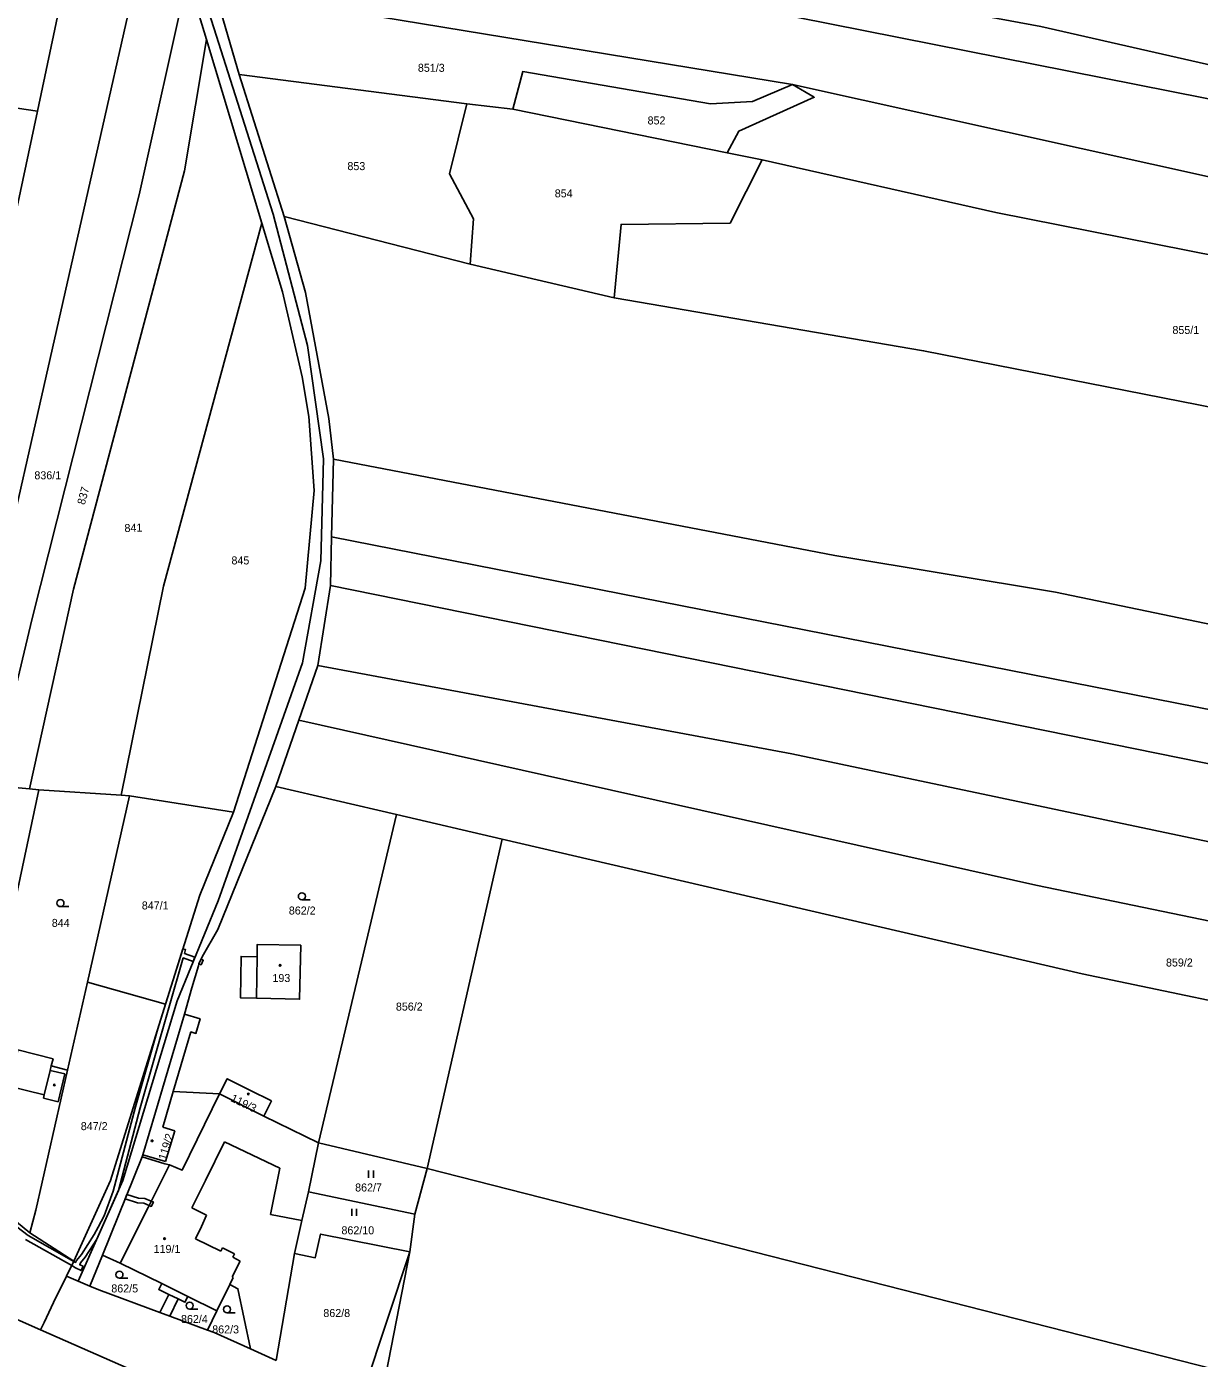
# Model space of a CAD drawing. Extents: x -776734 to -748832, y -1118122 to -976986.
# Drawn here: x -752662.5 to -752413.4, y -1114263.1 to -1113980.3 of the extents above; entities that cross this region are included whole.
import ezdxf

# ---------------------------------------------------------------- set-up
doc = ezdxf.new("R2010")
doc.units = 0
for name, color, linetype in [('KM_Hranice obce', 7, 'Continuous'), ('KM_Hranice parcel', 7, 'Continuous'), ('KM_Parcelní čísla', 7, 'Continuous'), ('KM_Vnitřní kresba', 7, 'Continuous'), ('KM_Věcná břemena k části', 7, 'Continuous'), ('KM_Značky budov', 7, 'Continuous'), ('KM_Značky kultur', 7, 'Continuous')]:
    doc.layers.add(name, color=color, linetype=linetype)

msp = doc.modelspace()

# ---------------------------------------------------------------- linework, layer by layer
at = {"layer": 'KM_Hranice obce'}
for p, q in [((-752624.32, -1113982.98), (-752628.32, -1113969.72)), ((-752624.32, -1113982.98), (-752628.32, -1113969.72)), ((-752612.54, -1114022), (-752624.32, -1113982.98)), ((-752612.54, -1114022), (-752624.32, -1113982.98)), ((-752618.58, -1114147.1), (-752603.37, -1114099.53)), ((-752618.58, -1114147.1), (-752603.37, -1114099.53)), ((-752618.58, -1114147.1), (-752625.74, -1114164.68)), ((-752618.58, -1114147.1), (-752625.74, -1114164.68)), ((-752625.74, -1114164.68), (-752632.98, -1114187.86)), ((-752625.74, -1114164.68), (-752632.98, -1114187.86)), ((-752632.98, -1114187.86), (-752644.66, -1114225.27)), ((-752632.98, -1114187.86), (-752644.66, -1114225.27)), ((-752644.66, -1114225.27), (-752652.49, -1114242.44)), ((-752644.66, -1114225.27), (-752652.49, -1114242.44)), ((-752654.02, -1114245.64), (-752652.49, -1114242.44)), ((-752654.02, -1114245.64), (-752652.49, -1114242.44)), ((-752637.21, -1114266.89), (-752659.53, -1114257.03)), ((-752637.21, -1114266.89), (-752659.53, -1114257.03))]:
    msp.add_line(p, q, dxfattribs=at)
for points in [[(-752603.37, -1114099.53), (-752601.44, -1114078.8), (-752602.54, -1114063.06), (-752603.98, -1114054.63), (-752608.14, -1114036.59), (-752612.54, -1114022)], [(-752603.37, -1114099.53), (-752601.44, -1114078.8), (-752602.54, -1114063.06), (-752603.98, -1114054.63), (-752608.14, -1114036.59), (-752612.54, -1114022)], [(-752654.02, -1114245.64), (-752656.77, -1114251.23), (-752658.78, -1114255.48), (-752659.53, -1114257.03)], [(-752654.02, -1114245.64), (-752656.77, -1114251.23), (-752658.78, -1114255.48), (-752659.53, -1114257.03)]]:
    msp.add_lwpolyline(points, dxfattribs=at)
at = {"layer": 'KM_Hranice parcel'}
for p, q in [((-752622.66, -1113972.37), (-752499.87, -1113992.53)), ((-752622.66, -1113972.37), (-752617.37, -1113990.44)), ((-752617.37, -1113990.44), (-752569.04, -1113996.68)), ((-752617.37, -1113990.44), (-752607.79, -1114020.59)), ((-752684.5, -1113994.68), (-752660.17, -1113998.22)), ((-752559.25, -1113997.81), (-752569.04, -1113996.68)), ((-752676.52, -1114074.55), (-752660.17, -1113998.22)), ((-752513.72, -1114007.03), (-752559.25, -1113997.81)), ((-752506.32, -1114008.53), (-752513.72, -1114007.03)), ((-752607.79, -1114020.59), (-752568.27, -1114030.7)), ((-752568.27, -1114030.7), (-752537.69, -1114037.85)), ((-752597.3, -1114072.12), (-752597.75, -1114088.6)), ((-752597.75, -1114088.6), (-752597.94, -1114098.95)), ((-752597.94, -1114098.95), (-752600.66, -1114115.91)), ((-752600.66, -1114115.91), (-752604.7, -1114127.56)), ((-752604.7, -1114127.56), (-752609.56, -1114141.64)), ((-752661.89, -1114142.16), (-752669.79, -1114141.43)), ((-752583.93, -1114147.59), (-752609.56, -1114141.64)), ((-752671.57, -1114197.14), (-752659.94, -1114142.34)), ((-752659.94, -1114142.34), (-752661.89, -1114142.16)), ((-752659.94, -1114142.34), (-752642.44, -1114143.5)), ((-752649.61, -1114183.2), (-752640.69, -1114143.61)), ((-752640.69, -1114143.61), (-752642.44, -1114143.5)), ((-752640.69, -1114143.61), (-752618.58, -1114147.1)), ((-752583.93, -1114147.59), (-752600.55, -1114217.27)), ((-752561.51, -1114152.79), (-752583.93, -1114147.59)), ((-752561.51, -1114152.79), (-752577.41, -1114222.73)), ((-752653.82, -1114201.87), (-752649.61, -1114183.2)), ((-752632.98, -1114187.86), (-752649.61, -1114183.2)), ((-752653.82, -1114201.87), (-752657.26, -1114200.95)), ((-752612.15, -1114211.63), (-752621.53, -1114206.91)), ((-752615.08, -1114206.1), (-752610.52, -1114208.39)), ((-752610.52, -1114208.39), (-752612.15, -1114211.63)), ((-752600.55, -1114217.27), (-752612.15, -1114211.63)), ((-752602.64, -1114227.73), (-752600.55, -1114217.27)), ((-752600.55, -1114217.27), (-752577.41, -1114222.73)), ((-752637.96, -1114220.3), (-752646.41, -1114241.15)), ((-752637.83, -1114219.88), (-752637.96, -1114220.3)), ((-752577.41, -1114222.73), (-752580.08, -1114232.48)), ((-752577.41, -1114222.73), (-752261.96, -1114303.31)), ((-752602.64, -1114227.73), (-752580.08, -1114232.48)), ((-752580.08, -1114232.48), (-752581.12, -1114240.48)), ((-752652.49, -1114242.44), (-752661.82, -1114236.39)), ((-752609.53, -1114263.52), (-752605.61, -1114240.78)), ((-752591.45, -1114271.64), (-752581.12, -1114240.48)), ((-752581.12, -1114240.48), (-752587.58, -1114273.63)), ((-752646.41, -1114241.15), (-752649.08, -1114247.74)), ((-752651.56, -1114246.69), (-752654.02, -1114245.64)), ((-752649.08, -1114247.74), (-752651.56, -1114246.69)), ((-752675.36, -1114250.03), (-752659.53, -1114257.03)), ((-752632.06, -1114254.13), (-752634.18, -1114253.35)), ((-752624.1, -1114257.08), (-752632.06, -1114254.13)), ((-752622.11, -1114252.99), (-752624.1, -1114257.08)), ((-752609.53, -1114263.52), (-752614.99, -1114261.06))]:
    msp.add_line(p, q, dxfattribs=at)
for points in [[(-752660.17, -1113998.22), (-752649.17, -1113945.86), (-752636.58, -1113861.93)], [(-752678.87, -1114140.59), (-752672.75, -1114117.71), (-752634.26, -1113948.04)], [(-752629.41, -1113948.98), (-752585.83, -1113954.56), (-752447.12, -1113980.26), (-752366.49, -1113998.56), (-752302.62, -1114009.92), (-752091.61, -1114053.03), (-752041.07, -1114064.86)], [(-752631.31, -1113953.54), (-752610.14, -1114020.09), (-752602.83, -1114047.96), (-752599.42, -1114072.05), (-752600, -1114093.73), (-752603.9, -1114115.37), (-752621.86, -1114165.9), (-752630.52, -1114187.13), (-752642.04, -1114225.29), (-752651.56, -1114246.69)], [(-752627.08, -1113957.06), (-752604.93, -1113959.33), (-752571.28, -1113963.89), (-752412.19, -1113995.48), (-752207.66, -1114037.55), (-752102.65, -1114057.53), (-752047.85, -1114070.07)], [(-752669.79, -1114141.43), (-752661.32, -1114105.94), (-752638.63, -1114015.99), (-752628.32, -1113969.72)], [(-752661.89, -1114142.16), (-752652.52, -1114099.74), (-752628.95, -1114010.91), (-752624.32, -1113982.98)], [(-752559.25, -1113997.81), (-752557.15, -1113989.79), (-752517.23, -1113996.65), (-752508.35, -1113996.15), (-752499.87, -1113992.53)], [(-752499.87, -1113992.53), (-752495.22, -1113995.25), (-752511.24, -1114002.44), (-752513.72, -1114007.03)], [(-752499.87, -1113992.53), (-752362.22, -1114023.06), (-752062.55, -1114081.38)], [(-752569.04, -1113996.68), (-752572.66, -1114011.49), (-752567.61, -1114021.04), (-752568.27, -1114030.7)], [(-752537.69, -1114037.85), (-752536.24, -1114022.25), (-752513.09, -1114022.03), (-752506.32, -1114008.53)], [(-752506.32, -1114008.53), (-752456.63, -1114019.7), (-752287.08, -1114053.29)], [(-752642.44, -1114143.5), (-752633.41, -1114099.08), (-752612.54, -1114022)], [(-752607.79, -1114020.59), (-752603.31, -1114036.69), (-752598.32, -1114063.49), (-752597.3, -1114072.12)], [(-752537.69, -1114037.85), (-752472.01, -1114049.1), (-752292.47, -1114084.38)], [(-752597.3, -1114072.12), (-752490.87, -1114092.55), (-752444.01, -1114100.34), (-752224.88, -1114145.98), (-752205.64, -1114151.37), (-752164.4, -1114166.46)], [(-752597.75, -1114088.6), (-752392.3, -1114129.05), (-752201.71, -1114173.64), (-752186.15, -1114178.78), (-752179.37, -1114182.19)], [(-752597.94, -1114098.95), (-752379.62, -1114143.27), (-752289.31, -1114163.83), (-752265.19, -1114168.89), (-752210.09, -1114183.65), (-752194.52, -1114190.14), (-752187.95, -1114193.84)], [(-752600.66, -1114115.91), (-752500.02, -1114134.7), (-752268, -1114183.59), (-752194.69, -1114203.88)], [(-752604.7, -1114127.56), (-752448.14, -1114162.61), (-752291.43, -1114195.01), (-752203.87, -1114217.11)], [(-752609.56, -1114141.64), (-752621.87, -1114172.01), (-752625.22, -1114177.82)], [(-752213.55, -1114231.19), (-752291.97, -1114212.01), (-752438.3, -1114181.41), (-752561.51, -1114152.79)], [(-752604.27, -1114175.32), (-752613.51, -1114175.16), (-752613.55, -1114177.77), (-752616.95, -1114177.72), (-752617.09, -1114186.5), (-752613.68, -1114186.56)], [(-752613.68, -1114186.56), (-752604.53, -1114186.82), (-752604.27, -1114175.32)], [(-752625.22, -1114177.82), (-752625.9, -1114179.27), (-752626.03, -1114179.72), (-752627.44, -1114184.42), (-752628.97, -1114190)], [(-752628.97, -1114190), (-752635.14, -1114210.78), (-752637.83, -1114219.88)], [(-752621.53, -1114206.91), (-752631.35, -1114206.39), (-752627.61, -1114193.75), (-752626.56, -1114194.06), (-752625.65, -1114190.98), (-752628.97, -1114190)], [(-752657.26, -1114200.95), (-752656.88, -1114199.45), (-752664.34, -1114197.58), (-752664.69, -1114198.97)], [(-752661.82, -1114236.39), (-752660.52, -1114231.58), (-752653.82, -1114201.87)], [(-752621.53, -1114206.91), (-752619.91, -1114203.68), (-752615.08, -1114206.1)], [(-752621.53, -1114206.91), (-752629.5, -1114223.12), (-752632.14, -1114221.97), (-752633.15, -1114221.73), (-752637.96, -1114220.3)], [(-752677.13, -1114223.28), (-752664.65, -1114234.09), (-752661.82, -1114236.39)], [(-752605.61, -1114240.78), (-752604.05, -1114233.82), (-752602.64, -1114227.73)], [(-752581.12, -1114240.48), (-752600.06, -1114236.7), (-752601.21, -1114241.71), (-752605.61, -1114240.78)], [(-752646.41, -1114241.15), (-752642.65, -1114242.88), (-752633.82, -1114247.17), (-752634.44, -1114248.43), (-752632.29, -1114249.49), (-752634.18, -1114253.35)], [(-752634.18, -1114253.35), (-752647.18, -1114248.54), (-752649.08, -1114247.74)], [(-752622.11, -1114252.99), (-752619.37, -1114247.42), (-752617.62, -1114248.31), (-752614.99, -1114261.06)], [(-752632.06, -1114254.13), (-752630.32, -1114250.46), (-752628.89, -1114251.17), (-752628.25, -1114249.97), (-752622.11, -1114252.99)], [(-752614.99, -1114261.06), (-752622.64, -1114257.62), (-752624.1, -1114257.08)]]:
    msp.add_lwpolyline(points, dxfattribs=at)
at = {"layer": 'KM_Vnitřní kresba'}
for p, q in [((-752613.68, -1114186.56), (-752613.55, -1114177.77)), ((-752657.48, -1114201.91), (-752657.26, -1114200.95)), ((-752658.78, -1114207.12), (-752657.48, -1114201.91)), ((-752657.48, -1114201.91), (-752654.41, -1114202.64)), ((-752654.41, -1114202.64), (-752655.84, -1114208.6)), ((-752633.6, -1114213.98), (-752631.35, -1114206.39)), ((-752658.93, -1114207.82), (-752658.78, -1114207.12)), ((-752655.84, -1114208.6), (-752658.93, -1114207.82)), ((-752631.01, -1114214.75), (-752633.6, -1114213.98)), ((-752631.01, -1114214.75), (-752633.02, -1114221.3)), ((-752624.55, -1114225.29), (-752620.51, -1114217.07)), ((-752620.51, -1114217.07), (-752608.72, -1114222.67)), ((-752637.83, -1114219.88), (-752633.02, -1114221.3)), ((-752632.14, -1114221.97), (-752635.79, -1114229.22)), ((-752610.71, -1114232.5), (-752608.72, -1114222.67)), ((-752624.55, -1114225.29), (-752627.42, -1114231.13)), ((-752635.79, -1114229.22), (-752636.7, -1114231.03)), ((-752636.7, -1114231.03), (-752642.65, -1114242.88)), ((-752624.3, -1114232.67), (-752627.42, -1114231.13)), ((-752625.34, -1114235.06), (-752626.64, -1114237.71)), ((-752625.34, -1114235.06), (-752624.3, -1114232.67)), ((-752610.71, -1114232.5), (-752604.05, -1114233.82)), ((-752621.23, -1114240.33), (-752626.64, -1114237.71)), ((-752620.87, -1114239.59), (-752621.23, -1114240.33)), ((-752618.33, -1114240.85), (-752620.87, -1114239.59)), ((-752618.7, -1114241.59), (-752618.33, -1114240.85)), ((-752618.82, -1114245.77), (-752617.16, -1114242.41)), ((-752617.16, -1114242.41), (-752618.7, -1114241.59)), ((-752619.37, -1114247.42), (-752618.61, -1114245.87)), ((-752618.61, -1114245.87), (-752618.82, -1114245.77)), ((-752633.82, -1114247.17), (-752628.25, -1114249.97)), ((-752632.29, -1114249.49), (-752630.32, -1114250.46))]:
    msp.add_line(p, q, dxfattribs=at)
msp.add_lwpolyline([(-752664.69, -1114198.97), (-752666.26, -1114205.28), (-752658.78, -1114207.12)], dxfattribs=at)
at = {"layer": 'KM_Věcná břemena k části'}
for points in [[(-752652.14, -1114243.84), (-752650.94, -1114244.43), (-752650.5, -1114243.53), (-752651.22, -1114243.18), (-752651.03, -1114242.82), (-752650.04, -1114241.62), (-752647.59, -1114237.77), (-752643.01, -1114227.46), (-752638.41, -1114209.89), (-752629.23, -1114178.03), (-752627.14, -1114178.83), (-752626.76, -1114177.91), (-752628.97, -1114177.07), (-752628.76, -1114176.26), (-752629.31, -1114176.12), (-752634.61, -1114193.09), (-752639.38, -1114209.65), (-752644.13, -1114227.57), (-752646.04, -1114232.82), (-752647.3, -1114235.24), (-752648.15, -1114236.79), (-752650.85, -1114241.03), (-752651.89, -1114242.28), (-752652.11, -1114242.71), (-752652.51, -1114242.48), (-752652.94, -1114243.38)], [(-752625.46, -1114178.32), (-752625.9, -1114179.27), (-752625.45, -1114179.48), (-752625, -1114178.53)], [(-752638.77, -1114229.06), (-752641.19, -1114228.26), (-752641.57, -1114229.2), (-752638.95, -1114230.06), (-752637.64, -1114230.11), (-752636.47, -1114230.58), (-752636.03, -1114230.8), (-752635.57, -1114229.9), (-752636.02, -1114229.68), (-752637.42, -1114229.12)]]:
    msp.add_lwpolyline(points, close=True, dxfattribs=at)
msp.add_lwpolyline([(-752662.74, -1114237.85), (-752652.94, -1114243.38), (-752652.51, -1114242.48), (-752662.18, -1114237.01), (-752666.7, -1114233.55)], dxfattribs=at)
at = {"layer": 'KM_Značky budov'}
for centre in [(-752608.6668, -1114179.6092), (-752656.6168, -1114205.0092), (-752615.4168, -1114206.9492), (-752635.8468, -1114216.8792), (-752633.2168, -1114237.6592)]:
    msp.add_circle(centre, 0.175, dxfattribs=at)
at = {"layer": 'KM_Značky kultur'}
for p, q in [((-752655.323, -1114167.15), (-752653.573, -1114167.15)), ((-752604.043, -1114165.7), (-752602.293, -1114165.7)), ((-752589.861, -1114224.71), (-752589.861, -1114223.21)), ((-752588.86, -1114224.71), (-752588.86, -1114223.21)), ((-752593.431, -1114232.79), (-752593.431, -1114231.29)), ((-752592.43, -1114232.79), (-752592.43, -1114231.29)), ((-752642.793, -1114246.06), (-752641.043, -1114246.06)), ((-752627.883, -1114252.62), (-752626.133, -1114252.62)), ((-752619.933, -1114253.42), (-752618.183, -1114253.42))]:
    msp.add_line(p, q, dxfattribs=at)
for centre in [(-752604.0429, -1114164.9498), (-752655.3229, -1114166.3998), (-752642.7929, -1114245.3098), (-752627.8829, -1114251.8698), (-752619.9329, -1114252.6698)]:
    msp.add_circle(centre, 0.75, dxfattribs=at)

# ---------------------------------------------------------------- texts
at = {"layer": 'KM_Parcelní čísla'}
for s, p in [('851/3', (-752579.408, -1113989.85)), ('852', (-752530.625, -1114001.03)), ('853', (-752594.375, -1114010.73)), ('854', (-752550.335, -1114016.51)), ('855/1', (-752419.148, -1114045.53)), ('836/1', (-752660.86, -1114076.39)), ('845', (-752619, -1114094.47)), ('847/1', (-752638.04, -1114167.74)), ('862/2', (-752606.818, -1114168.82)), ('844', (-752657.16, -1114171.45)), ('859/2', (-752420.518, -1114179.86)), ('193', (-752610.3, -1114183.15)), ('856/2', (-752584.078, -1114189.22)), ('847/2', (-752651, -1114214.61)), ('862/7', (-752592.738, -1114227.64)), ('862/10', (-752595.64, -1114236.73)), ('119/1', (-752635.54, -1114240.69)), ('862/5', (-752644.518, -1114249.08)), ('862/4', (-752629.718, -1114255.57)), ('862/8', (-752599.488, -1114254.3)), ('862/3', (-752623.088, -1114257.78))]:
    msp.add_text(s, height=1.7, dxfattribs=at).set_placement(p)
for s, rotation, p in [('837', 75, (-752650.168, -1114081.919)), ('841', 2, (-752641.69, -1114087.609)), ('119/3', 334, (-752619.322, -1114208.403)), ('119/2', 73, (-752632.951, -1114221.082))]:
    msp.add_text(s, height=1.7, rotation=rotation, dxfattribs=at).set_placement(p)

doc.saveas('drawing.dxf')
